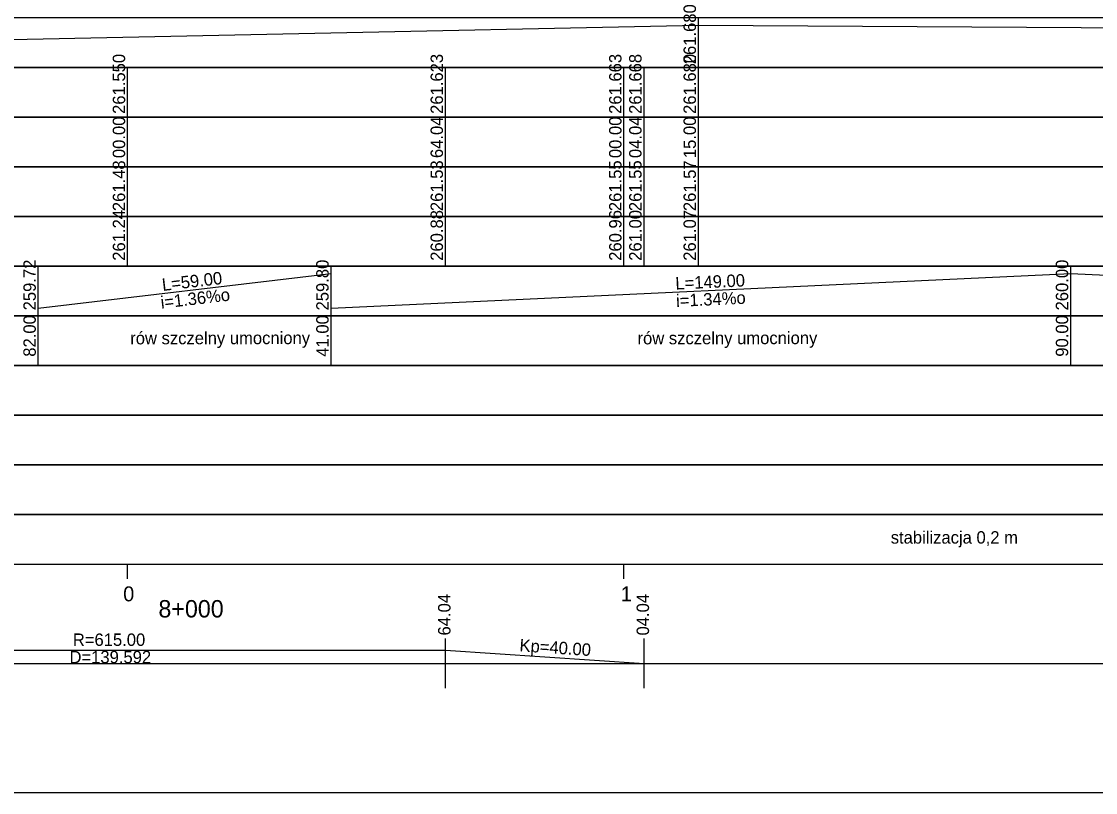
# Model space of a CAD drawing. Extents: x 6445630 to 6518227, y 5499240 to 5511716.
# Drawn here: x 6452609.8 to 6452826.2, y 5506751.3 to 5506906.6 of the extents above; entities that cross this region are included whole.
import ezdxf

# ---------------------------------------------------------------- set-up
doc = ezdxf.new("R2010")
doc.units = 0
for name, color, linetype in [('TOR_PROF-tabelka-geometria T1', 7, 'Continuous'), ('TOR_PROF-tabelka-kilometracja', 7, 'Continuous'), ('TOR_PROF-tabelka-odleglosci T1', 7, 'Continuous'), ('TOR_PROF-tabelka-pochylenia proj T1', 7, 'Continuous'), ('TOR_PROF-tabelka-rodzaj rowu T1', 7, 'Continuous'), ('TOR_PROF-tabelka-rowyT1', 7, 'Continuous'), ('TOR_PROF-tabelka-rurociagi T1', 7, 'Continuous'), ('TOR_PROF-tabelka-rzedne istn T1', 7, 'Continuous'), ('TOR_PROF-tabelka-rzedne proj T1', 7, 'Continuous'), ('TOR_PROF-tabelka-teren istniejacy T1', 7, 'Continuous'), ('TOR_PROF-tabelka-warstwa ochronna T1', 7, 'Continuous'), ('TOR_PROF-warstwa ochronna', 7, 'Continuous'), ('TOR_RAMKI-MASKA WYCIECIA', 7, 'Continuous')]:
    doc.layers.add(name, color=color, linetype=linetype)

msp = doc.modelspace()

# ---------------------------------------------------------------- linework, layer by layer
at = {"layer": 'TOR_PROF-tabelka-geometria T1'}
for points in [[(6452695.25, 5506772.3), (6452695.25, 5506782.3)], [(6452735.25, 5506772.3), (6452735.25, 5506782.3)], [(6452423.2, 5506777.3), (6452515.66, 5506777.3), (6452515.66, 5506777.3), (6452555.66, 5506779.97), (6452555.66, 5506779.97), (6452695.25, 5506779.97), (6452695.25, 5506779.97), (6452735.25, 5506777.3), (6452735.25, 5506777.3), (6458247.17, 5506777.3)], [(6452331.21, 5506777.3), (6459531.21, 5506777.3)]]:
    msp.add_lwpolyline(points, dxfattribs=at)
at = {"layer": 'TOR_PROF-tabelka-kilometracja'}
for points in [[(6452631.21, 5506794.3), (6452631.21, 5506797.3)], [(6452631.21, 5506794.3), (6452631.21, 5506797.3)], [(6452731.21, 5506794.3), (6452731.21, 5506797.3)]]:
    msp.add_lwpolyline(points, dxfattribs=at)
at = {"layer": 'TOR_PROF-tabelka-odleglosci T1'}
msp.add_lwpolyline([(6452331.21, 5506877.3), (6459531.21, 5506877.3), (6459531.21, 5506887.3), (6452331.21, 5506887.3)], close=True, dxfattribs=at)
for points in [[(6452631.21, 5506877.3), (6452631.21, 5506887.3)], [(6452695.25, 5506877.3), (6452695.25, 5506887.3)], [(6452731.21, 5506877.3), (6452731.21, 5506887.3)], [(6452735.25, 5506877.3), (6452735.25, 5506887.3)], [(6452746.21, 5506877.3), (6452746.21, 5506887.3)]]:
    msp.add_lwpolyline(points, dxfattribs=at)
at = {"layer": 'TOR_PROF-tabelka-pochylenia proj T1'}
msp.add_lwpolyline([(6452331.21, 5506897.3), (6459531.21, 5506897.3), (6459531.21, 5506907.3), (6452331.21, 5506907.3)], close=True, dxfattribs=at)
for points in [[(6452746.21, 5506897.3), (6452746.21, 5506907.3)], [(6452411.21, 5506898.8), (6452746.21, 5506905.8)], [(6452746.21, 5506905.8), (6453891.74, 5506898.8)]]:
    msp.add_lwpolyline(points, dxfattribs=at)
at = {"layer": 'TOR_PROF-tabelka-rodzaj rowu T1'}
for points in [[(6452331.21, 5506837.3), (6459531.21, 5506837.3), (6459531.21, 5506847.3), (6452331.21, 5506847.3)], [(6452331.21, 5506817.3), (6459531.21, 5506817.3), (6459531.21, 5506827.3), (6452331.21, 5506827.3)]]:
    msp.add_lwpolyline(points, close=True, dxfattribs=at)
for points in [[(6452613.21, 5506837.3), (6452613.21, 5506847.3)], [(6452672.21, 5506837.3), (6452672.21, 5506847.3)], [(6452821.21, 5506837.3), (6452821.21, 5506847.3)]]:
    msp.add_lwpolyline(points, dxfattribs=at)
at = {"layer": 'TOR_PROF-tabelka-rowyT1'}
msp.add_lwpolyline([(6452331.21, 5506847.3), (6459531.21, 5506847.3), (6459531.21, 5506857.3), (6452331.21, 5506857.3)], close=True, dxfattribs=at)
for points in [[(6452613.21, 5506847.3), (6452613.21, 5506857.3)], [(6452672.21, 5506847.3), (6452672.21, 5506857.3)], [(6452821.21, 5506847.3), (6452821.21, 5506857.3)], [(6452613.21, 5506848.8), (6452672.21, 5506855.8)], [(6452672.21, 5506848.8), (6452821.21, 5506855.8)], [(6452821.21, 5506855.8), (6452971.21, 5506848.8)]]:
    msp.add_lwpolyline(points, dxfattribs=at)
at = {"layer": 'TOR_PROF-tabelka-rurociagi T1'}
msp.add_lwpolyline([(6452331.21, 5506827.3), (6459531.21, 5506827.3), (6459531.21, 5506837.3), (6452331.21, 5506837.3)], close=True, dxfattribs=at)
at = {"layer": 'TOR_PROF-tabelka-rzedne istn T1'}
msp.add_lwpolyline([(6452331.21, 5506867.3), (6459531.21, 5506867.3), (6459531.21, 5506877.3), (6452331.21, 5506877.3)], close=True, dxfattribs=at)
for points in [[(6452631.21, 5506867.3), (6452631.21, 5506877.3)], [(6452695.25, 5506867.3), (6452695.25, 5506877.3)], [(6452731.21, 5506867.3), (6452731.21, 5506877.3)], [(6452735.25, 5506867.3), (6452735.25, 5506877.3)], [(6452746.21, 5506867.3), (6452746.21, 5506877.3)], [(6452631.21, 5506857.3), (6452631.21, 5506867.3)], [(6452631.21, 5506857.3), (6452631.21, 5506867.3)], [(6452631.21, 5506857.3), (6452631.21, 5506867.3)], [(6452695.25, 5506857.3), (6452695.25, 5506867.3)], [(6452695.25, 5506857.3), (6452695.25, 5506867.3)], [(6452695.25, 5506857.3), (6452695.25, 5506867.3)], [(6452731.21, 5506857.3), (6452731.21, 5506867.3)], [(6452731.21, 5506857.3), (6452731.21, 5506867.3)], [(6452731.21, 5506857.3), (6452731.21, 5506867.3)], [(6452735.25, 5506857.3), (6452735.25, 5506867.3)], [(6452735.25, 5506857.3), (6452735.25, 5506867.3)], [(6452735.25, 5506857.3), (6452735.25, 5506867.3)], [(6452746.21, 5506857.3), (6452746.21, 5506867.3)]]:
    msp.add_lwpolyline(points, dxfattribs=at)
at = {"layer": 'TOR_PROF-tabelka-rzedne proj T1'}
msp.add_lwpolyline([(6452331.21, 5506887.3), (6459531.21, 5506887.3), (6459531.21, 5506897.3), (6452331.21, 5506897.3)], close=True, dxfattribs=at)
for points in [[(6452631.21, 5506887.3), (6452631.21, 5506897.3)], [(6452695.25, 5506887.3), (6452695.25, 5506897.3)], [(6452731.21, 5506887.3), (6452731.21, 5506897.3)], [(6452735.25, 5506887.3), (6452735.25, 5506897.3)], [(6452746.21, 5506887.3), (6452746.21, 5506897.3)]]:
    msp.add_lwpolyline(points, dxfattribs=at)
at = {"layer": 'TOR_PROF-tabelka-teren istniejacy T1'}
msp.add_lwpolyline([(6452331.21, 5506857.3), (6459531.21, 5506857.3), (6459531.21, 5506867.3), (6452331.21, 5506867.3)], close=True, dxfattribs=at)
msp.add_lwpolyline([(6452331.21, 5506857.3), (6459531.21, 5506857.3), (6459531.21, 5506867.3), (6452331.21, 5506867.3)], close=True, dxfattribs=at)
msp.add_lwpolyline([(6452331.21, 5506857.3), (6459531.21, 5506857.3), (6459531.21, 5506867.3), (6452331.21, 5506867.3)], close=True, dxfattribs=at)
at = {"layer": 'TOR_PROF-tabelka-warstwa ochronna T1'}
msp.add_lwpolyline([(6452331.21, 5506807.3), (6459531.21, 5506807.3), (6459531.21, 5506817.3), (6452331.21, 5506817.3)], close=True, dxfattribs=at)
at = {"layer": 'TOR_PROF-warstwa ochronna'}
msp.add_lwpolyline([(6452331.21, 5506797.3), (6459531.21, 5506797.3), (6459531.21, 5506807.3), (6452331.21, 5506807.3)], close=True, dxfattribs=at)
at = {"layer": 'TOR_RAMKI-MASKA WYCIECIA'}
msp.add_lwpolyline([(6452266.27, 5506751.3), (6453906.27, 5506751.3), (6453906.27, 5507038.3), (6452266.27, 5507038.3)], close=True, dxfattribs=at)

# ---------------------------------------------------------------- texts
at = {"layer": 'TOR_PROF-tabelka-geometria T1'}
for s, p in [('R=615.00', (6452620.17, 5506780.82)), ('D=139.592', (6452619.5, 5506777.32))]:
    msp.add_text(s, height=2.5, dxfattribs=at).set_placement(p)
msp.add_text('Kp=40.00', height=2.5, rotation=356.1859, dxfattribs=at).set_placement((6452710.1, 5506779.73))
at = {"layer": 'TOR_PROF-tabelka-kilometracja'}
for s, p in [('0', (6452630.32, 5506789.8)), ('1', (6452730.56, 5506789.8))]:
    msp.add_text(s, height=3, dxfattribs=at).set_placement(p)
msp.add_text('8+000', height=3.5, rotation=360, dxfattribs=at).set_placement((6452637.42, 5506786.55))
at = {"layer": 'TOR_PROF-tabelka-odleglosci T1'}
for s, p in [('00.00', (6452630.71, 5506879.04)), ('64.04', (6452694.75, 5506879.05)), ('00.00', (6452730.71, 5506879.04)), ('04.04', (6452734.75, 5506879.05)), ('15.00', (6452745.71, 5506879.04)), ('64.04', (6452696.26, 5506782.92)), ('04.04', (6452736.26, 5506782.92))]:
    msp.add_text(s, height=2.5, rotation=90, dxfattribs=at).set_placement(p)
at = {"layer": 'TOR_PROF-tabelka-pochylenia proj T1'}
msp.add_text('261.680', height=2.5, rotation=90, dxfattribs=at).set_placement((6452745.71, 5506897.94))
at = {"layer": 'TOR_PROF-tabelka-rodzaj rowu T1'}
for s, p in [('82.00', (6452612.71, 5506839.05)), ('41.00', (6452671.71, 5506839.05)), ('90.00', (6452820.71, 5506839.05))]:
    msp.add_text(s, height=2.5, rotation=90, dxfattribs=at).set_placement(p)
at = {"layer": 'TOR_PROF-tabelka-rowyT1'}
for s, rotation, p in [('259.72', 90, (6452612.71, 5506848.38)), ('259.80', 90, (6452671.71, 5506848.37)), ('260.00', 90, (6452820.71, 5506848.37)), ('L=59.00', 6.7662, (6452638.29, 5506852.28)), ('L=149.00', 2.6898, (6452741.62, 5506852.56)), ('i=1.36%o', 6.7662, (6452638.01, 5506848.72)), ('i=1.34%o', 2.6898, (6452741.76, 5506849.07)), ('rów szczelny umocniony', 0.087, (6452631.74, 5506841.54)), ('rów szczelny umocniony', 0.087, (6452733.94, 5506841.54))]:
    msp.add_text(s, height=2.5, rotation=rotation, dxfattribs=at).set_placement(p)
at = {"layer": 'TOR_PROF-tabelka-rzedne istn T1'}
for s, p in [('261.48', (6452630.71, 5506868.36)), ('261.53', (6452694.75, 5506868.37)), ('261.55', (6452730.71, 5506868.36)), ('261.55', (6452734.75, 5506868.36)), ('261.57', (6452745.71, 5506868.37)), ('261.24', (6452630.71, 5506858.37)), ('260.88', (6452694.75, 5506858.36)), ('260.96', (6452730.71, 5506858.36)), ('261.00', (6452734.75, 5506858.37)), ('261.07', (6452745.71, 5506858.37))]:
    msp.add_text(s, height=2.5, rotation=90, dxfattribs=at).set_placement(p)
at = {"layer": 'TOR_PROF-tabelka-rzedne proj T1'}
for s, p in [('261.550', (6452630.71, 5506887.94)), ('261.623', (6452694.75, 5506887.94)), ('261.663', (6452730.71, 5506887.94)), ('261.668', (6452734.75, 5506887.94)), ('261.680', (6452745.71, 5506887.94))]:
    msp.add_text(s, height=2.5, rotation=90, dxfattribs=at).set_placement(p)
at = {"layer": 'TOR_PROF-warstwa ochronna'}
msp.add_text('stabilizacja 0,2 m', height=2.5, dxfattribs=at).set_placement((6452784.95, 5506801.42))

doc.saveas('drawing.dxf')
